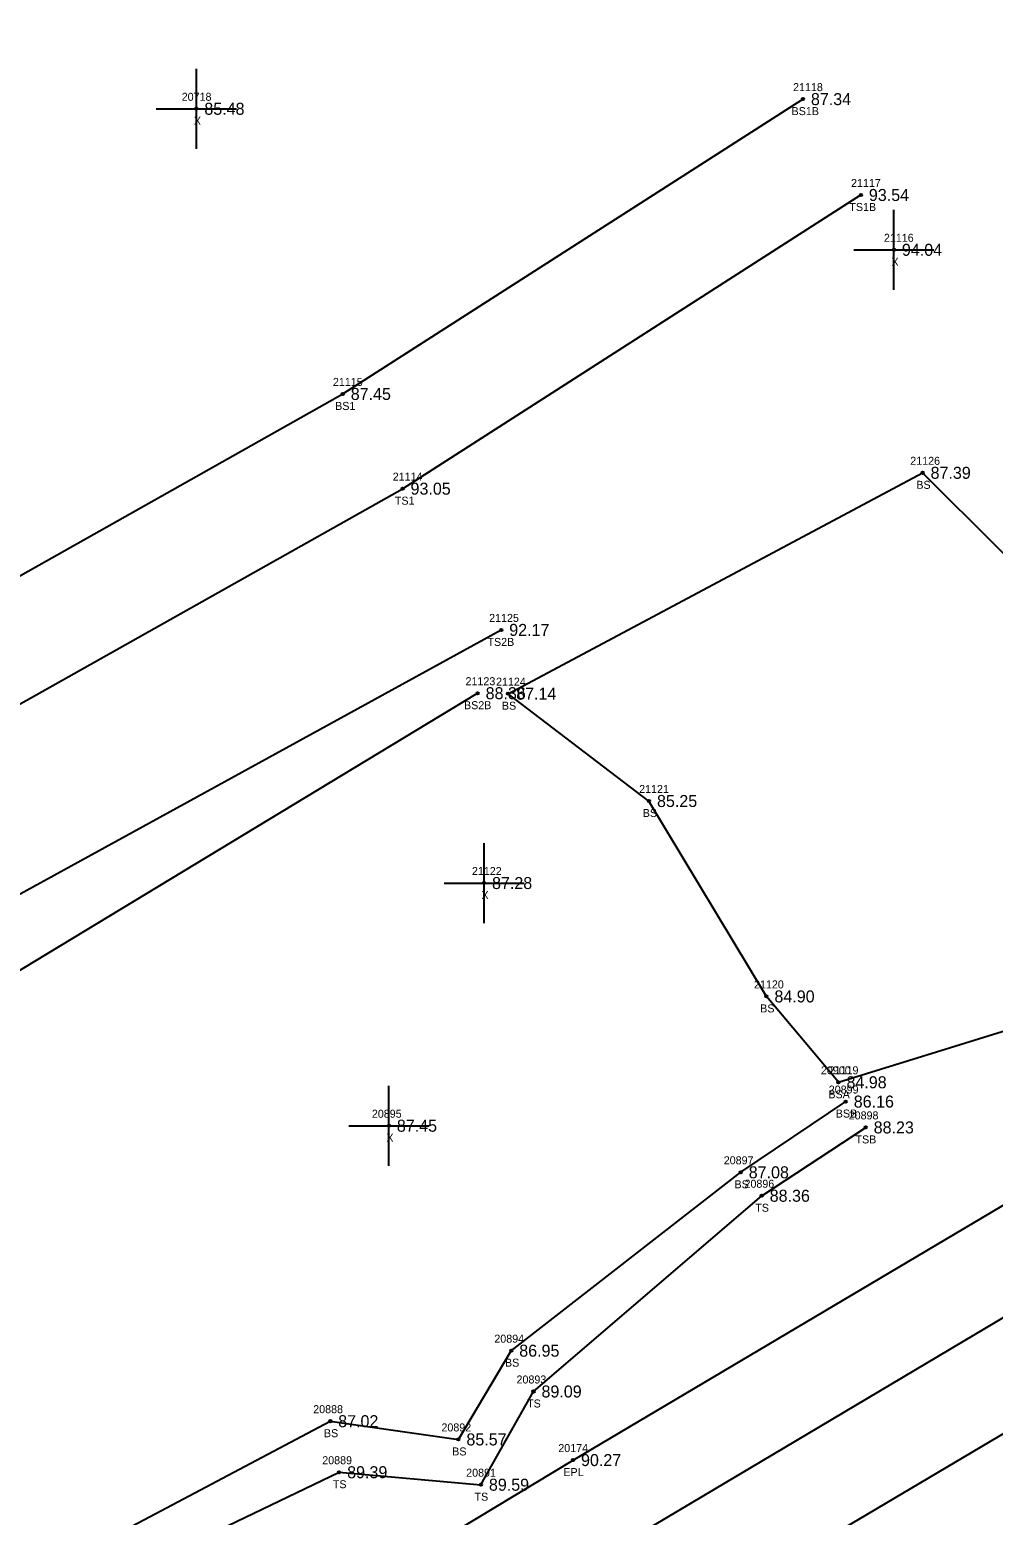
# Model space of a CAD drawing. Extents: x 2530197 to 2532051, y 935230 to 936631.
# Drawn here: x 2531392.5 to 2531512.9, y 936167.6 to 936353.2 of the extents above; entities that cross this region are included whole.
import ezdxf

# ---------------------------------------------------------------- set-up
doc = ezdxf.new("R2010")
doc.units = 0
for name, color, linetype in [('RD_DTM_BkLn1', 7, 'Continuous'), ('RD_DTM_BkLn2', 7, 'Continuous'), ('RD_DTM_BkLn_txCode', 7, 'Continuous'), ('RD_EX_Misc', 7, 'Continuous'), ('RD_EX_Misc_txCode', 7, 'Continuous'), ('RD_EX_Road', 7, 'Continuous'), ('RD_EX_Road_txCode', 7, 'Continuous'), ('RD_EX_TX_Misc_ELEV', 7, 'Continuous'), ('RD_EX_TX_Road_ELEV', 7, 'Continuous'), ('RD_SMD_Locator', 7, 'Continuous')]:
    doc.layers.add(name, color=color, linetype=linetype)

msp = doc.modelspace()

# ---------------------------------------------------------------- linework, layer by layer
at = {"layer": 'RD_DTM_BkLn1'}
msp.add_lwpolyline([(2531175.16, 935992.09), (2531214.08, 936014.93), (2531297.2, 936064.16), (2531382.2, 936114.3), (2531466.12, 936163.77), (2531548.89, 936212.96), (2531632.55, 936261.89), (2531678, 936289.19), (2531722.34, 936315.93), (2531754.26, 936342.49), (2531759.78, 936349.83), (2531772.77, 936373.29), (2531778.96, 936389.71), (2531793.78, 936438.29), (2531813.65, 936511.36), (2531832.39, 936582.88)], dxfattribs=at)
at = {"layer": 'RD_DTM_BkLn2'}
for points in [[(2531151.41, 935999.3), (2531167.24, 936008.08), (2531181.24, 936018.79), (2531181.58, 936027.3), (2531178.12, 936073.45), (2531167.63, 936105.68), (2531166.35, 936111.09), (2531158.41, 936111.85), (2531152.62, 936122.31), (2531150.51, 936125.78), (2531152.42, 936137.74), (2531230.98, 936186.53), (2531313.57, 936233.84), (2531368.67, 936272.3), (2531431.6, 936307.72), (2531489.09, 936344.56)], [(2531153.52, 936135.49), (2531238.65, 936176.03), (2531319.12, 936225.52), (2531376.31, 936260.58), (2531439.07, 936295.88), (2531496.33, 936332.58)], [(2531493.53, 936221.7), (2531484.53, 936232.43), (2531469.86, 936256.85), (2531452.26, 936270.26), (2531504.04, 936297.86), (2531523.09, 936278.85), (2531539.04, 936254.79), (2531543.31, 936250.79), (2531544.84, 936248.43)], [(2531229.61, 936049.23), (2531205.83, 936108.6), (2531204.82, 936125.4), (2531213.43, 936143.32), (2531245.76, 936164.18), (2531307.39, 936201.57), (2531320.27, 936194.22), (2531339.05, 936206.18), (2531339.67, 936220.33), (2531381.85, 936240.08), (2531451.4, 936278.23)], [(2531232.8, 936067.46), (2531215.52, 936108.97), (2531226.2, 936132.67), (2531251.54, 936152.54), (2531308.69, 936190.88), (2531325.04, 936186.59), (2531344.92, 936198.09), (2531350.73, 936212.74), (2531384.02, 936231.34), (2531448.45, 936270.32)], [(2531493.53, 936221.7), (2531520.97, 936230.22), (2531544.84, 936248.43)], [(2531232.8, 936067.46), (2531281.18, 936092.01), (2531356.28, 936135.72), (2531362.71, 936151.65), (2531400.38, 936163.66), (2531430.03, 936179.35), (2531446.05, 936177.07), (2531452.65, 936188.16), (2531481.32, 936210.45), (2531494.44, 936219.29)], [(2531229.61, 936049.23), (2531287.21, 936081.23), (2531360.99, 936124.94), (2531368.39, 936145.81), (2531399.09, 936157.58), (2531431.15, 936172.97), (2531448.86, 936171.41), (2531455.43, 936183.06), (2531483.94, 936207.52), (2531496.93, 936216.06)]]:
    msp.add_lwpolyline(points, dxfattribs=at)
at = {"layer": 'RD_EX_Misc'}
for p, q in [((2531413.31, 936338.35), (2531413.31, 936348.35)), ((2531408.31, 936343.35), (2531418.31, 936343.35)), ((2531500.46, 936320.73), (2531500.46, 936330.73)), ((2531495.46, 936325.73), (2531505.46, 936325.73)), ((2531449.25, 936241.6), (2531449.25, 936251.6)), ((2531444.25, 936246.6), (2531454.25, 936246.6)), ((2531437.36, 936211.27), (2531437.36, 936221.27)), ((2531432.36, 936216.27), (2531442.36, 936216.27))]:
    msp.add_line(p, q, dxfattribs=at)
at = {"layer": 'RD_EX_Road'}
for points in [[(2531169.65, 936000.77), (2531208.79, 936024.95), (2531292.04, 936074.02), (2531376.24, 936123.7), (2531460.37, 936174.49), (2531542.92, 936223.44), (2531626.67, 936270.85), (2531672.4, 936298.39), (2531714.28, 936327.21), (2531747.19, 936360.45), (2531761.42, 936377.32), (2531773.11, 936411.11), (2531782.2, 936441.65), (2531803.17, 936514.76), (2531820.28, 936585.8)], [(2531180.82, 935982), (2531220.82, 936004.21), (2531303.54, 936053.39), (2531388.75, 936103.71), (2531472.27, 936152.98), (2531554.79, 936201.9), (2531638.11, 936250.92), (2531683.19, 936278.28), (2531730.37, 936304.55), (2531771.5, 936341.26), (2531788.67, 936375.53), (2531805.57, 936434.84), (2531825.53, 936508.74), (2531844.13, 936579.65)]]:
    msp.add_lwpolyline(points, dxfattribs=at)
at = {"layer": 'RD_SMD_Locator'}
for centre in [(2531413.31, 936343.35), (2531489.09, 936344.56), (2531496.33, 936332.58), (2531500.46, 936325.73), (2531431.6, 936307.72), (2531504.04, 936297.86), (2531439.07, 936295.88), (2531451.4, 936278.23), (2531448.45, 936270.32), (2531452.26, 936270.26), (2531469.86, 936256.85), (2531449.25, 936246.6), (2531484.53, 936232.43), (2531493.53, 936221.7), (2531493.53, 936221.7), (2531494.44, 936219.29), (2531437.36, 936216.27), (2531496.93, 936216.06), (2531481.32, 936210.45), (2531483.94, 936207.52), (2531452.65, 936188.16), (2531455.43, 936183.06), (2531430.03, 936179.35), (2531446.05, 936177.07), (2531460.37, 936174.49), (2531431.15, 936172.97), (2531448.86, 936171.41)]:
    msp.add_circle(centre, 0.15, dxfattribs=at)

# ---------------------------------------------------------------- texts
at = {"layer": 'RD_DTM_BkLn_txCode'}
for s, p in [('21118', (2531487.86, 936345.56)), ('BS1B', (2531487.67, 936342.56)), ('21117', (2531495.1, 936333.58)), ('TS1B', (2531494.89, 936330.58)), ('21115', (2531430.37, 936308.72)), ('BS1', (2531430.65, 936305.72)), ('21126', (2531502.5, 936298.86)), ('21114', (2531437.84, 936296.88)), ('BS', (2531503.26, 936295.86)), ('TS1', (2531438.11, 936293.88)), ('21125', (2531449.89, 936279.23)), ('TS2B', (2531449.68, 936276.23)), ('21123', (2531446.94, 936271.32)), ('21124', (2531450.75, 936271.26)), ('BS2B', (2531446.75, 936268.32)), ('BS', (2531451.48, 936268.26)), ('21121', (2531468.63, 936257.85)), ('BS', (2531469.08, 936254.85)), ('21120', (2531482.98, 936233.43)), ('BS', (2531483.75, 936230.43)), ('20900', (2531491.34, 936222.7)), ('21119', (2531492.31, 936222.7)), ('20899', (2531492.32, 936220.29)), ('BSA', (2531492.27, 936219.7)), ('BSA', (2531492.27, 936219.7)), ('BSB', (2531493.19, 936217.29)), ('20898', (2531494.81, 936217.06)), ('TSB', (2531495.66, 936214.06)), ('20897', (2531479.2, 936211.45)), ('BS', (2531480.54, 936208.45)), ('20896', (2531481.79, 936208.52)), ('TS', (2531483.14, 936205.52)), ('20894', (2531450.54, 936189.16)), ('BS', (2531451.87, 936186.16)), ('20893', (2531453.31, 936184.06)), ('TS', (2531454.63, 936181.06)), ('20888', (2531427.91, 936180.35)), ('BS', (2531429.25, 936177.35)), ('20892', (2531443.93, 936178.07)), ('20889', (2531429.04, 936173.97)), ('BS', (2531445.27, 936175.07)), ('20891', (2531447.02, 936172.41)), ('TS', (2531430.36, 936170.97)), ('TS', (2531448.06, 936169.41))]:
    msp.add_text(s, height=1, dxfattribs=at).set_placement(p)
at = {"layer": 'RD_EX_Misc_txCode'}
for s, p in [('20718', (2531411.48, 936344.35)), ('X', (2531413, 936341.35)), ('21116', (2531499.21, 936326.73)), ('X', (2531500.15, 936323.73)), ('21122', (2531447.74, 936247.6)), ('X', (2531448.93, 936244.6)), ('20895', (2531435.24, 936217.27)), ('X', (2531437.05, 936214.27))]:
    msp.add_text(s, height=1, dxfattribs=at).set_placement(p)
at = {"layer": 'RD_EX_Road_txCode'}
for s, p in [('20174', (2531458.53, 936175.49)), ('EPL', (2531459.16, 936172.49))]:
    msp.add_text(s, height=1, dxfattribs=at).set_placement(p)
at = {"layer": 'RD_EX_TX_Misc_ELEV'}
for s, p in [('87.34', (2531490.09, 936343.81)), ('85.48', (2531414.31, 936342.6)), ('93.54', (2531497.33, 936331.83)), ('94.04', (2531501.46, 936324.98)), ('87.45', (2531432.6, 936306.97)), ('87.39', (2531505.04, 936297.11)), ('93.05', (2531440.07, 936295.13)), ('92.17', (2531452.4, 936277.48)), ('88.36', (2531449.45, 936269.57)), ('87.14', (2531453.26, 936269.51)), ('85.25', (2531470.86, 936256.1)), ('87.28', (2531450.25, 936245.85)), ('84.90', (2531485.53, 936231.68)), ('84.98', (2531494.53, 936220.95)), ('84.98', (2531494.53, 936220.95)), ('86.16', (2531495.44, 936218.54)), ('87.45', (2531438.36, 936215.52)), ('88.23', (2531497.93, 936215.31)), ('87.08', (2531482.32, 936209.7)), ('88.36', (2531484.94, 936206.77)), ('86.95', (2531453.65, 936187.41)), ('89.09', (2531456.43, 936182.31)), ('87.02', (2531431.03, 936178.6)), ('85.57', (2531447.05, 936176.32)), ('89.39', (2531432.15, 936172.22)), ('89.59', (2531449.86, 936170.66))]:
    msp.add_text(s, height=1.5, dxfattribs=at).set_placement(p)
at = {"layer": 'RD_EX_TX_Road_ELEV'}
msp.add_text('90.27', height=1.5, dxfattribs=at).set_placement((2531461.37, 936173.74))

doc.saveas('drawing.dxf')
